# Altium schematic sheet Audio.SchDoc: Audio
size A4; DocumentNumber: MB1165; Revision: C.1; SheetNumber: 5; SheetTotal: 17; Project: STM32469I-EVAL
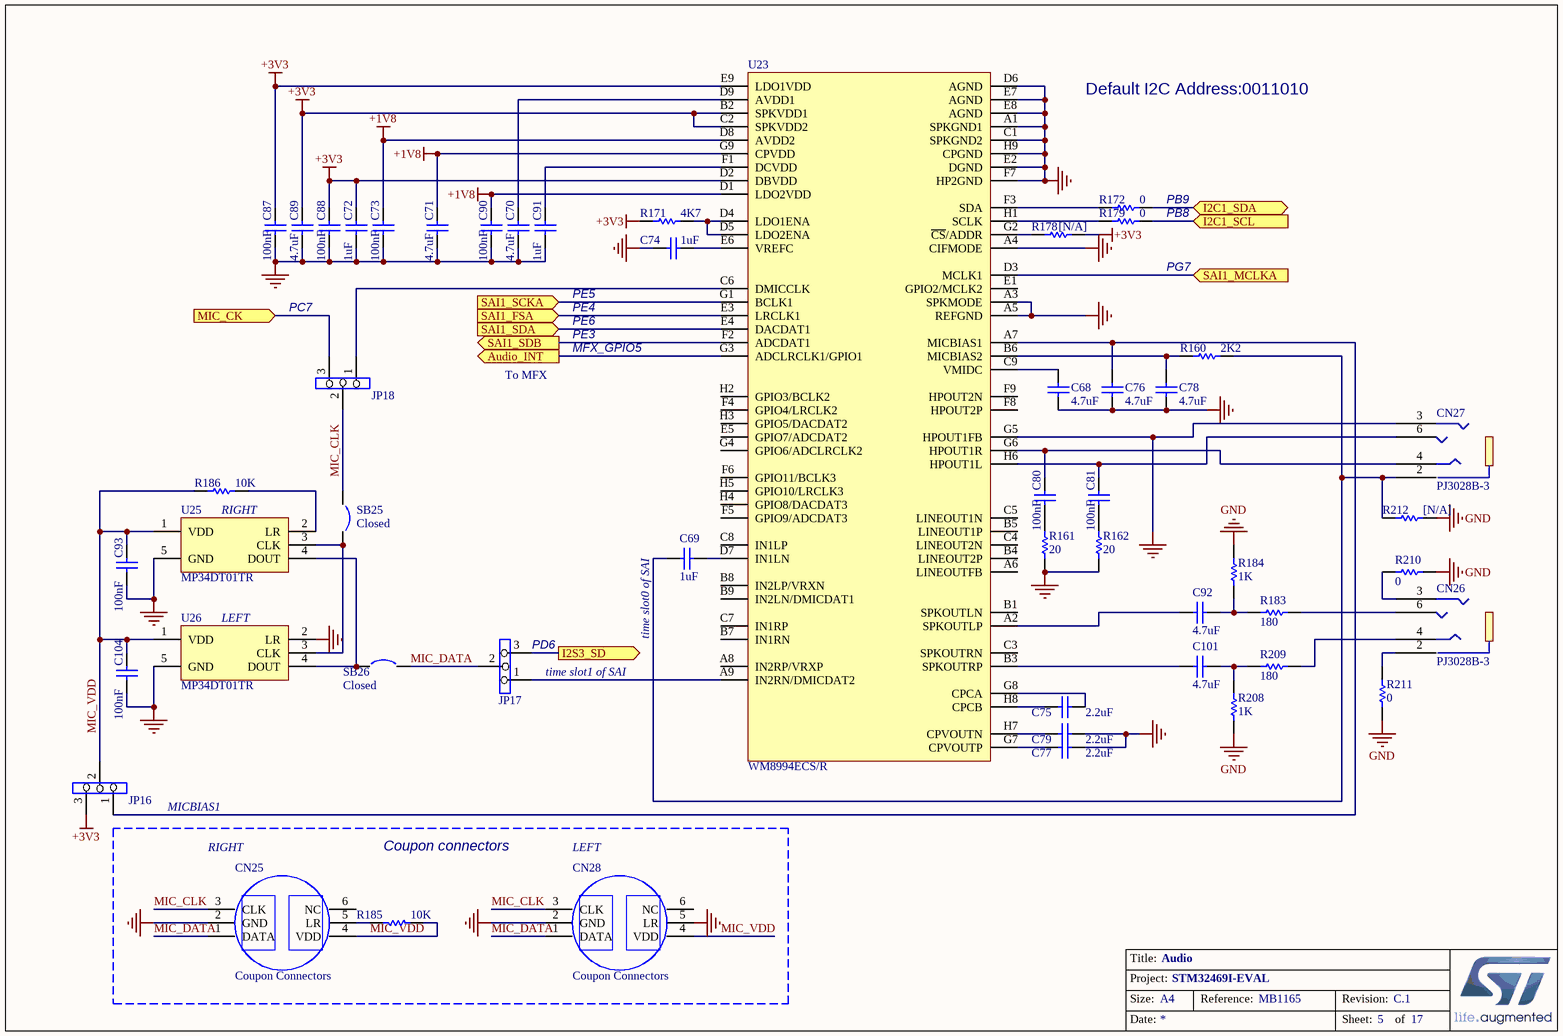
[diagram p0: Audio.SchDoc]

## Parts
C68  4.7uF  [0603C]
C69  1uF  [0603C]
C70  4.7uF  [0603C]
C71  4.7uF  [0603C]
C72  1uF  [0603C]
C73  100nF  [0603C]
C74  1uF  [0603C]
C75  2.2uF  [0603C]
C76  4.7uF  [0603C]
C77  2.2uF  [0603C]
C78  4.7uF  [0603C]
C79  2.2uF  [0603C]
C80  100nF  [0603C]
C81  100nF  [0603C]
C87  100nF  [0603C]
C88  100nF  [0603C]
C89  4.7uF  [0603C]
C90  100nF  [0603C]
C91  1uF  [0603C]
C92  4.7uF  [0603C]
C93  100nF  [0603C]
C101  4.7uF  [0603C]
C104  100nF  [0603C]
CN25  Coupon Connectors  [Coupon]
CN26  PJ3028B-3  [PJ3028B]
CN27  PJ3028B-3  [PJ3028B]
CN28  Coupon Connectors  [Coupon]
JP16  (no value)  [SIP3]
JP17  (no value)  [SIP3]
JP18  (no value)  [SIP3]
R160  2K2  [0603R]
R161  20  [0603R]
R162  20  [0603R]
R171  4K7  [0603R]
R172  0  [0603R]
R178  [N/A]  [0603R]
R179  0  [0603R]
R183  180  [0402R]
R184  1K  [0402R]
R185  10K  [0603R]
R186  10K  [0603R]
R208  1K  [0402R]
R209  180  [0402R]
R210  0  [0603R]
R211  0  [0603R]
R212  [N/A]  [0603R]
SB25  Closed  [SB_0603]
SB26  Closed  [SB_0603]
U23  WM8994ECS/R  [BGA72_0R5_4R5X4]
U25  MP34DT01TR  [MP34DT01TR]
U26  MP34DT01TR  [MP34DT01TR]

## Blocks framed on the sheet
Coupon connectors: CN25 CN28 R185

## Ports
Audio_INT (out), I2C1_SCL (in), I2C1_SDA (bidir), I2S3_SD (out), MIC_CK (in), SAI1_FSA (in), SAI1_MCLKA (in), SAI1_SCKA (in), SAI1_SDA (in), SAI1_SDB (out)

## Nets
+1V8: C71.1 C73.1 C90.1 U23.D1(LDO2VDD) U23.D8(AVDD2) U23.G9(CPVDD)
+3V3: C72.1 C87.1 C88.1 C89.1 JP16.3 R171.2 R178.1 U23.B2(SPKVDD1) U23.C2(SPKVDD2) U23.D2(DBVDD) U23.E9(LDO1VDD)
GND: C68.1 C70.2 C71.2 C72.2 C73.2 C74.2 C76.1 C77.2 C78.1 C79.2 C87.2 C88.2 C89.2 C90.2 C91.2 C93.2 C104.2 CN25.2(GND) CN27.3 CN28.2(GND) CN28.5(LR) R161.2 R162.2 R184.2 R208.1 R210.2 R211.2 R212.1 U23.A1(SPKGND1) U23.A3(SPKMODE) U23.A4(CIFMODE) U23.A5(REFGND) U23.C1(SPKGND2) U23.D6(AGND) U23.E2(DGND) U23.E7(AGND) U23.E8(AGND) U23.F7(HP2GND) U23.G5(HPOUT1FB) U23.H9(CPGND) U25.5(GND) U26.2(LR) U26.5(GND)
Audio_INT: U23.G3(ADCLRCLK1/GPIO1) ; port Audio_INT
I2C1_SCL: R179.1 ; port I2C1_SCL
I2C1_SDA: R172.1 ; port I2C1_SDA
I2S3_SD: JP17.3 ; port I2S3_SD
MIC_CK: JP18.3 ; port MIC_CK
MIC_CLK: CN25.3(CLK) CN28.3(CLK) JP18.2 SB25.1
MIC_DATA: CN25.1(DATA) CN28.1(DATA) JP17.2 SB26.2
MIC_VDD: C93.1 C104.1 CN25.4(VDD) CN28.4(VDD) JP16.2 R185.2 R186.2 U25.1(VDD) U26.1(VDD)
SAI1_FSA: U23.E3(LRCLK1) ; port SAI1_FSA
SAI1_MCLKA: U23.D3(MCLK1) ; port SAI1_MCLKA
SAI1_SCKA: U23.G1(BCLK1) ; port SAI1_SCKA
SAI1_SDA: U23.E4(DACDAT1) ; port SAI1_SDA
SAI1_SDB: U23.F2(ADCDAT1) ; port SAI1_SDB
NetC68_2: C68.2 U23.C9(VMIDC)
NetC69_1: C69.1 U23.D7(IN1LN)
NetC69_2: C69.2 CN27.2 R160.1 R212.2
NetC70_1: C70.1 U23.D9(AVDD1)
NetC74_1: C74.1 U23.E6(VREFC)
NetC75_1: C75.1 U23.H8(CPCB)
NetC75_2: C75.2 U23.G8(CPCA)
NetC76_2: C76.2 JP16.1 U23.A7(MICBIAS1)
NetC77_1: C77.1 U23.G7(CPVOUTP)
NetC78_2: C78.2 R160.2 U23.B6(MICBIAS2)
NetC79_1: C79.1 U23.H7(CPVOUTN)
NetC80_1: C80.1 CN27.4 U23.G6(HPOUT1R)
NetC80_2: C80.2 R161.1
NetC81_1: C81.1 CN27.6 U23.H6(HPOUT1L)
NetC81_2: C81.2 R162.1
NetC91_1: C91.1 U23.F1(DCVDD)
NetC92_1: C92.1 R183.1 R184.1
NetC92_2: C92.2 U23.A2(SPKOUTLP)
NetC101_1: C101.1 R208.2 R209.2
NetC101_2: C101.2 U23.B3(SPKOUTRP)
NetCN25_5: CN25.5(LR) R185.1
NetCN26_2: CN26.2 R211.1
NetCN26_3: CN26.3 R210.1
NetCN26_4: CN26.4 R209.1
NetCN26_6: CN26.6 R183.2
NetJP17_1: JP17.1 U23.A9(IN2RN/DMICDAT2)
NetJP18_1: JP18.1 U23.C6(DMICCLK)
NetR171_1: R171.1 U23.D4(LDO1ENA) U23.D5(LDO2ENA)
NetR172_2: R172.2 U23.F3(SDA)
NetR178_2: R178.2 U23.G2(~{CS}/ADDR)
NetR179_2: R179.2 U23.H1(SCLK)
NetR186_1: R186.1 U25.2(LR)
NetSB25_2: SB25.2 U25.3(CLK) U26.3(CLK)
NetSB26_1: SB26.1 U25.4(DOUT) U26.4(DOUT)

Not connected (* = marked no-connect by the designer): CN25 6(NC); CN28 6(NC); U23 A6(LINEOUTFB) A8(IN2RP/VRXP) B1(SPKOUTLN) B4(LINEOUT2P) B5(LINEOUT1P) B7(IN1RN) B8(IN2LP/VRXN) B9(IN2LN/DMICDAT1) C3(SPKOUTRN) C4(LINEOUT2N) C5(LINEOUT1N) C7(IN1RP) C8(IN1LP) E1(GPIO2/MCLK2) E5(GPIO7/ADCDAT2) F4(GPIO4/LRCLK2) F5(GPIO9/ADCDAT3) F6(GPIO11/BCLK3) F8(HPOUT2P) F9(HPOUT2N) G4(GPIO6/ADCLRCLK2) H2(GPIO3/BCLK2) H3(GPIO5/DACDAT2) H4(GPIO8/DACDAT3) H5(GPIO10/LRCLK3)

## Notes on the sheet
- Default I2C Address:0011010
- PB9
- PB8
- PC7
- PE5
- PE4
- PG7
- To MFX
- PE6
- PE3
- MFX_GPIO5
- RIGHT
- (near U26) LEFT
- (near JP17) PD6
- (near C69) time slot0 of SAI
- (near JP17) time slot1 of SAI
- MICBIAS1
- LEFT

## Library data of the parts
C68 C70 C71 C73 C76 C78 C80 C81 C87-C90 C93 C104 = Cap: Capacitor; Value: 10nF
C69 C72 C74 C75 C77 C79 C91 = CAP: Capacitor; Value: 100nF
C92 C101 = Cap: Capacitor; Value: 10nF; Ordered by: Subcon
CN25 CN28 = Coupon Connectors: Header, 3-Pin, Single row
JP16-JP18 = Jumper3
R160-R162 R171 R172 R178 R179 R185 R186 R212 = Res1: Resistor; Value: 1K
R183 R209-R211 = Res1: Resistor; Value: 1K; Ordered by: Subcon
R184 R208 = Res1: Resistor; Ordered by: Subcon
SB25 SB26 = Circuit Breaker_close: Circuit Breaker
U25 U26 = MP34DT01TR: MEMS audio sensor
